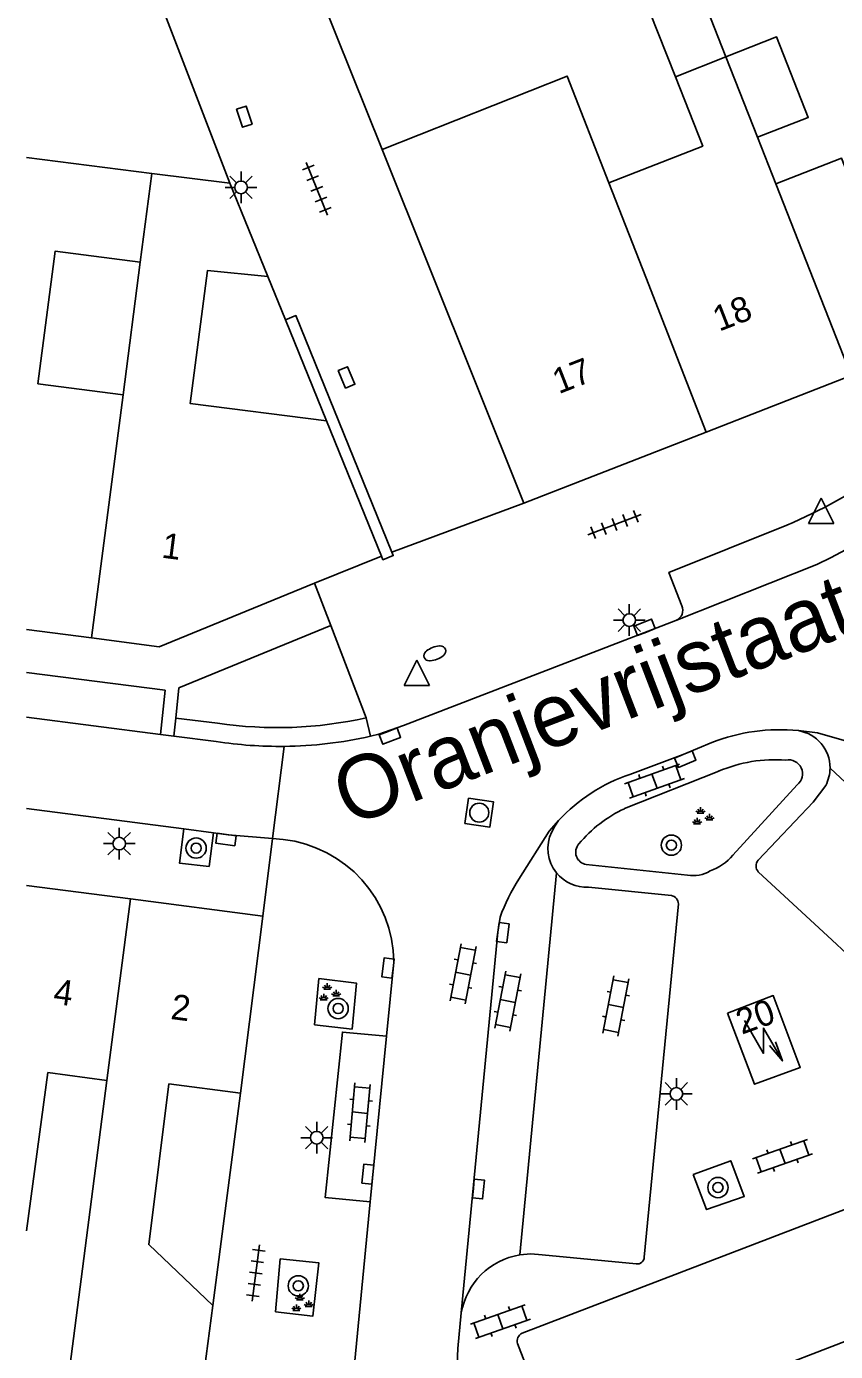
# Model space of a CAD drawing. Extents: x 132994 to 136000, y 393499 to 395512.
# Drawn here: x 133000 to 133031.9, y 395339 to 395391.3 of the extents above; entities that cross this region are included whole.
import ezdxf

# ---------------------------------------------------------------- set-up
doc = ezdxf.new("R2010")
doc.units = 0
for name, color, linetype in [('gg-afsc-erfafscheiding', 7, 'Continuous'), ('gg-afsc-muur', 7, 'Continuous'), ('gg-anno-huisnummerreeks BGT', 7, 'Continuous'), ('gg-anno-openbare ruimte label', 7, 'Continuous'), ('gg-bbg-gedigitaliseerde bebouwing', 7, 'Continuous'), ('gg-bbg-gedigitaliseerde bijgebouw', 7, 'Continuous'), ('gg-bbg-hoofdgebouw', 7, 'Continuous'), ('gg-bbg-luifel en loopbrug', 7, 'Continuous'), ('gg-bbg-tussenscheiding', 7, 'Continuous'), ('gg-knt-verharding', 7, 'Continuous'), ('gg-knt-verharding nz', 7, 'Continuous'), ('gt-grn-weggrens', 7, 'Continuous'), ('gt-symb-boom', 7, 'Continuous'), ('gt-symb-brandkraan', 7, 'Continuous'), ('gt-symb-groenvak', 7, 'Continuous'), ('gt-symb-klinker verharding', 7, 'Continuous'), ('gt-symb-kolk', 7, 'Continuous'), ('gt-symb-lichtmast', 7, 'Continuous'), ('gt-symb-rioolschacht', 7, 'Continuous'), ('gt-symb-tegel verharding', 7, 'Continuous'), ('gt-symb-trafo symbool', 7, 'Continuous'), ('gt-symb-waterafsluiter', 7, 'Continuous')]:
    doc.layers.add(name, color=color, linetype=linetype)

# ---------------------------------------------------------------- blocks, each defined once
blk = doc.blocks.new('gt0-KOLK')
at = {"layer": 'gt-symb-kolk'}
blk.add_lwpolyline([(0, 0), (0.375, 0), (0.375, 0.4), (-0.375, 0.4), (-0.375, 0), (0, 0)], dxfattribs=at)
blk = doc.blocks.new('gt0-LMAST')
at = {"layer": 'gt-symb-lichtmast'}
for p, q in [((-0.005, 0.246), (-0.005, 0.621)), ((-0.182, 0.173), (-0.447, 0.438)), ((0.172, 0.173), (0.437, 0.438)), ((-0.255, -0.004), (-0.63, -0.004)), ((-0.182, -0.181), (-0.447, -0.446)), ((-0.005, -0.254), (-0.005, -0.629)), ((0.437, -0.446), (0.172, -0.181)), ((0.245, -0.004), (0.62, -0.004))]:
    blk.add_line(p, q, dxfattribs=at)
blk.add_circle((-0.005, -0.004), 0.25, dxfattribs=at)
blk = doc.blocks.new('gt0-TEG1')
at = {"layer": 'gt-symb-tegel verharding'}
for p, q in [((-1.125, 0), (1.125, 0)), ((-0.9, -0.25), (-0.9, 0.25)), ((-0.45, -0.25), (-0.45, 0.25)), ((0, -0.25), (0, 0.25)), ((0.45, -0.25), (0.45, 0.25)), ((0.9, -0.25), (0.9, 0.25))]:
    blk.add_line(p, q, dxfattribs=at)
blk = doc.blocks.new('gt0-WAFSL')
at = {"layer": 'gt-symb-waterafsluiter'}
for p, q in [((-0.5, -0.333), (0, 0.667)), ((0, 0.667), (0.5, -0.333)), ((0.5, -0.333), (-0.5, -0.333))]:
    blk.add_line(p, q, dxfattribs=at)
blk = doc.blocks.new('gt0-BR')
at = {"layer": 'gt-symb-brandkraan'}
for centre, radius, start, end in [((-0.244, 0), 0.206, 107.5669, 252.4331), ((0.599, -2.664), 3, 106.892, 107.5669), ((0, -0.691), 0.938, 73.108, 106.892), ((-0.599, -2.664), 3, 72.4331, 73.108), ((0.244, 0), 0.206, 287.567, 72.4331), ((0.599, 2.664), 3, 252.4331, 253.108), ((0, 0.691), 0.938, 253.108, 286.8921), ((-0.599, 2.664), 3, 286.8921, 287.567)]:
    blk.add_arc(centre, radius, start, end, dxfattribs=at)
blk = doc.blocks.new('gt0-GRVAK')
at = {"layer": 'gt-symb-groenvak'}
for p, q in [((-0.11, 0.189), (-0.228, 0.24)), ((-0.182, 0.153), (0.088, 0.153)), ((-0.091, 0.211), (-0.156, 0.322)), ((-0.047, 0.214), (-0.047, 0.393)), ((-0.004, 0.211), (0.061, 0.322)), ((0.015, 0.189), (0.133, 0.24)), ((0.262, -0.052), (0.197, 0.059)), ((0.305, -0.049), (0.305, 0.13)), ((0.349, -0.052), (0.414, 0.059)), ((-0.245, -0.228), (-0.363, -0.177)), ((-0.318, -0.264), (-0.047, -0.264)), ((-0.226, -0.206), (-0.291, -0.095)), ((-0.183, -0.203), (-0.183, -0.024)), ((-0.139, -0.206), (-0.074, -0.095)), ((-0.12, -0.228), (-0.002, -0.177)), ((0.243, -0.074), (0.125, -0.023)), ((0.17, -0.11), (0.441, -0.11)), ((0.368, -0.074), (0.486, -0.023))]:
    blk.add_line(p, q, dxfattribs=at)
blk = doc.blocks.new('gt0-BOOM')
at = {"layer": 'gt-symb-boom'}
for radius in [0.4, 0.2]:
    blk.add_circle((0, 0), radius, dxfattribs=at)
blk = doc.blocks.new('gt0-HSP')
at = {"layer": 'gt-symb-trafo symbool'}
for points in [[(0.771, 0.746), (-0.529, -0.004), (0.471, -0.004), (-0.829, -0.754)], [(-0.217, -0.24), (-0.829, -0.754), (-0.077, -0.48)]]:
    blk.add_lwpolyline(points, dxfattribs=at)
blk = doc.blocks.new('gt0-KL1')
at = {"layer": 'gt-symb-klinker verharding'}
for p, q in [((-1.15, 0.3), (1.15, 0.3)), ((-1, -0.3), (-1, 0.3)), ((-0.5, 0.3), (-0.5, 0.45)), ((0, -0.3), (0, 0.3)), ((0.5, 0.3), (0.5, 0.45)), ((1, -0.3), (1, 0.3)), ((-1.15, -0.3), (1.15, -0.3)), ((-0.5, -0.45), (-0.5, -0.3)), ((0.5, -0.45), (0.5, -0.3))]:
    blk.add_line(p, q, dxfattribs=at)
blk = doc.blocks.new('gt0-RS')
at = {"layer": 'gt-symb-rioolschacht'}
blk.add_lwpolyline([(-0.5, -0.5), (0.5, -0.5), (0.5, 0.5), (-0.5, 0.5)], close=True, dxfattribs=at)
blk.add_circle((0, 0), 0.375, dxfattribs=at)

msp = doc.modelspace()

# ---------------------------------------------------------------- linework, layer by layer
at = {"layer": 'gg-afsc-erfafscheiding'}
msp.add_line((133011.425, 395392.988), (133014.031, 395386.48), dxfattribs=at)
at = {"layer": 'gg-afsc-muur'}
for p, q in [((133008.03, 395385.145), (133003.697, 395396.435)), ((133009.529, 395381.461), (133010.22, 395379.755)), ((133010.22, 395379.755), (133011.838, 395375.763)), ((133008.45, 395349.22), (133007.35, 395340.833))]:
    msp.add_line(p, q, dxfattribs=at)
at = {"layer": 'gg-bbg-gedigitaliseerde bebouwing'}
for p, q in [((133025.611, 395389.356), (133027.607, 395390.141)), ((133028.856, 395386.964), (133029.578, 395385.124)), ((133004.49, 395382.025), (133003.812, 395376.796)), ((133001.705, 395338.403), (133003.17, 395349.719))]:
    msp.add_line(p, q, dxfattribs=at)
for points in [[(133014.031, 395386.48), (133021.341, 395389.381), (133022.986, 395385.162)], [(133022.986, 395385.162), (133026.687, 395386.616), (133025.611, 395389.356)], [(133029.578, 395385.124), (133032.169, 395386.133), (133032.704, 395384.759), (133035.66, 395385.91)], [(133003.812, 395376.796), (133000.447, 395377.233), (133001.125, 395382.461), (133004.49, 395382.025)], [(133000, 395343.773), (133000.842, 395350.031), (133003.17, 395349.719)]]:
    msp.add_lwpolyline(points, dxfattribs=at)
at = {"layer": 'gg-bbg-gedigitaliseerde bijgebouw'}
msp.add_lwpolyline([(133028.856, 395386.964), (133030.853, 395387.748), (133029.605, 395390.925), (133027.607, 395390.141)], dxfattribs=at)
at = {"layer": 'gg-bbg-hoofdgebouw'}
for p, q in [((133000, 395386.17), (133004.946, 395385.539)), ((133019.63, 395372.52), (133014.031, 395386.48)), ((133004.946, 395385.539), (133008.03, 395385.145)), ((133009.529, 395381.461), (133008.03, 395385.145)), ((133011.838, 395375.763), (133014.007, 395370.426)), ((133026.822, 395375.323), (133019.63, 395372.52)), ((133011.367, 395369.349), (133014.007, 395370.426)), ((133000, 395367.52), (133002.566, 395367.19)), ((133000, 395357.419), (133004.098, 395356.888)), ((133004.098, 395356.888), (133009.33, 395356.21)), ((133009.33, 395356.21), (133008.45, 395349.22)), ((133006.942, 395337.72), (133007.35, 395340.833))]:
    msp.add_line(p, q, dxfattribs=at)
for points in [[(133011.838, 395375.763), (133006.455, 395376.453), (133007.139, 395381.7), (133009.529, 395381.461)], [(133032.551, 395377.556), (133028.342, 395375.916), (133026.822, 395375.323)], [(133002.566, 395367.19), (133005.235, 395366.846), (133011.367, 395369.349)], [(133027.67, 395352.37), (133029.47, 395353.07), (133030.54, 395350.23), (133028.73, 395349.57), (133027.67, 395352.37)], [(133008.45, 395349.22), (133005.62, 395349.58), (133004.822, 395343.236), (133007.35, 395340.833)]]:
    msp.add_lwpolyline(points, dxfattribs=at)
at = {"layer": 'gg-bbg-luifel en loopbrug'}
msp.add_lwpolyline([(133025.611, 395389.356), (133024.251, 395392.816), (133026.248, 395393.601), (133027.607, 395390.141)], dxfattribs=at)
at = {"layer": 'gg-bbg-tussenscheiding'}
for p, q in [((133027.607, 395390.141), (133028.856, 395386.964)), ((133004.49, 395382.025), (133004.946, 395385.539)), ((133022.986, 395385.162), (133024.438, 395381.439)), ((133032.551, 395377.556), (133029.578, 395385.124)), ((133026.822, 395375.323), (133024.438, 395381.439)), ((133002.566, 395367.19), (133003.812, 395376.796)), ((133004.098, 395356.888), (133003.17, 395349.719))]:
    msp.add_line(p, q, dxfattribs=at)
at = {"layer": 'gg-knt-verharding'}
for p, q in [((133012.009, 395367.678), (133013.407, 395364.04)), ((133005.898, 395364.022), (133005.808, 395363.316)), ((133005.898, 395364.022), (133007.537, 395363.829)), ((133013.407, 395364.04), (133013.571, 395363.309)), ((133005.808, 395363.316), (133005.282, 395363.384)), ((133007.487, 395363.101), (133005.808, 395363.316)), ((133023.605, 395360.45), (133027.318, 395361.927)), ((133030.419, 395361.395), (133027.882, 395358.609)), ((133000, 395360.455), (133006.212, 395359.649)), ((133006.212, 395359.649), (133007.377, 395359.498)), ((133009.715, 395359.269), (133010.129, 395359.233)), ((133022.093, 395358.25), (133026.084, 395357.821)), ((133025.459, 395357.016), (133022.185, 395357.35)), ((133024.382, 395342.739), (133025.728, 395356.689)), ((133014.497, 395354.385), (133014.203, 395351.469)), ((133019.563, 395339.738), (133043.881, 395349.068)), ((133013.569, 395344.929), (133012.777, 395336.763)), ((133017.161, 395340.535), (133017.027, 395339.132)), ((133020.512, 395336.403), (133019.38, 395339.324))]:
    msp.add_line(p, q, dxfattribs=at)
for points in [[(133010.22, 395379.755), (133010.634, 395379.923), (133014.42, 395370.58)], [(133030.007, 395371.645), (133025.353, 395369.779), (133025.867, 395368.463)], [(133014.42, 395370.58), (133014.475, 395370.444), (133014.067, 395370.279), (133014.007, 395370.426)], [(133025.633, 395367.883), (133014.873, 395363.73), (133013.905, 395363.388), (133013.571, 395363.309)], [(133005.898, 395364.022), (133006.018, 395365.218), (133012.009, 395367.678)], [(133005.282, 395363.384), (133005.469, 395365.124), (133000, 395365.833)], [(133027.048, 395363.065), (133025.921, 395362.594), (133023.814, 395361.8)], [(133028.878, 395358.413), (133031.046, 395360.702), (133031.543, 395361.368)], [(133020.727, 395359.534), (133020.85, 395359.765), (133021, 395359.979)], [(133006.212, 395359.649), (133006.036, 395358.3), (133007.204, 395358.169), (133007.377, 395359.498)], [(133009.715, 395359.269), (133007.965, 395359.421), (133007.377, 395359.498)], [(133039.15, 395348.406), (133031.801, 395355.255), (133028.883, 395357.952)], [(133011.37, 395351.918), (133012.85, 395351.746), (133013.022, 395353.565), (133011.542, 395353.737), (133011.37, 395351.918)], [(133014.203, 395351.469), (133012.471, 395351.625), (133011.786, 395345.097), (133013.569, 395344.929)], [(133026.308, 395346.005), (133026.841, 395344.615), (133028.33, 395345.133), (133027.795, 395346.543), (133026.308, 395346.005)], [(133024.062, 395342.47), (133020.357, 395342.832), (133019.911, 395342.864), (133019.467, 395342.828)], [(133009.826, 395340.577), (133011.301, 395340.41), (133011.531, 395342.521), (133010.014, 395342.669), (133009.826, 395340.577)]]:
    msp.add_lwpolyline(points, dxfattribs=at)
for centre, radius, start, end in [((133021.106, 395392.421), 22.602, 293.1921, 315.334), ((133025.468, 395368.287), 0.436, 292.2492, 23.8077), ((133009.911, 395379.543), 15.893, 261.4095, 282.7078), ((133009.985, 395379.333), 16.423, 261.2511, 270.6595), ((133009.981, 395379.25), 16.34, 270.6751, 282.6898), ((133029.741, 395356.074), 7.492, 84.4723, 111.0685), ((133030.225, 395362.06), 1.49, 359.7727, 80.8008), ((133029.55, 395356.702), 5.682, 85.7228, 113.1319), ((133030.079, 395361.828), 0.55, 308.1297, 101.0242), ((133030.187, 395362.073), 1.528, 332.5455, 359.3034), ((133025.948, 395355.418), 6.729, 108.4859, 137.3296), ((133025.722, 395355.846), 5.067, 114.6888, 140.6327), ((133022.095, 395358.873), 1.519, 154.2168, 219.1002), ((133009.58, 395354.347), 4.917, 0.4449, 83.5922), ((133022.16, 395358.73), 0.485, 137.1629, 262.1089), ((133026.241, 395360.033), 2.172, 289.9615, 319.0501), ((133029.144, 395358.185), 0.35, 139.4792, 221.7636), ((133022.092, 395358.848), 1.501, 218.4423, 273.5574), ((133026.296, 395359.163), 1.359, 261.0308, 300.3854), ((133025.402, 395356.695), 0.326, 358.9111, 79.9724), ((133019.926, 395340.061), 2.805, 99.4095, 170.2666), ((133024.095, 395342.756), 0.288, 263.5156, 356.5869), ((133019.718, 395339.422), 0.352, 116.1433, 196.1631), ((133021.786, 395338.673), 4.781, 174.4878, 231.0728)]:
    msp.add_arc(centre, radius, start, end, dxfattribs=at)
at = {"layer": 'gg-knt-verharding nz'}
for p, q in [((133000, 395364.065), (133005.282, 395363.384)), ((133031.715, 395362.054), (133042.784, 395351.686)), ((133020.916, 395357.915), (133019.467, 395342.828)), ((133014.203, 395351.469), (133013.569, 395344.929)), ((133020.541, 395334.887), (133046.32, 395344.8))]:
    msp.add_line(p, q, dxfattribs=at)
for points in [[(133025.633, 395367.883), (133031.197, 395370.09), (133031.764, 395370.363), (133032.323, 395370.665), (133033.233, 395371.205)], [(133032.728, 395363.011), (133031.22, 395363.439), (133030.463, 395363.531)], [(133021, 395359.979), (133020.633, 395359.565), (133019.429, 395357.668)], [(133018.69, 395356.166), (133018.604, 395355.578), (133017.161, 395340.535)]]:
    msp.add_lwpolyline(points, dxfattribs=at)
msp.add_arc((133026.597, 395353.209), 8.442, 148.1123, 159.4924, dxfattribs=at)
at = {"layer": 'gt-grn-weggrens'}
for p, q in [((133019.63, 395372.52), (133014.42, 395370.58)), ((133012.009, 395367.678), (133011.367, 395369.349)), ((133010.174, 395362.911), (133009.715, 395359.269)), ((133009.715, 395359.269), (133009.33, 395356.21))]:
    msp.add_line(p, q, dxfattribs=at)

# ---------------------------------------------------------------- block references
at = {"layer": 'gt-symb-boom'}
for p in [(133006.693, 395358.894), (133025.45, 395359.01), (133012.297, 395352.557), (133027.291, 395345.488), (133010.727, 395341.607)]:
    msp.add_blockref('gt0-BOOM', p, dxfattribs=at)
at = {"layer": 'gt-symb-brandkraan', "rotation": 21.28016631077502}
msp.add_blockref('gt0-BR', (133016.115, 395366.583), dxfattribs=at)
at = {"layer": 'gt-symb-groenvak'}
for p in [(133026.649, 395360.113), (133011.914, 395353.163), (133010.834, 395340.897)]:
    msp.add_blockref('gt0-GRVAK', p, dxfattribs=at)
at = {"layer": 'gt-symb-klinker verharding'}
for p, rotation in [((133024.784, 395361.536), 19.503573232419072), ((133017.229, 395353.931), -100.89418298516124), ((133018.995, 395352.852), -100.89418298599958), ((133023.263, 395352.656), -100.89418298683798), ((133013.159, 395348.445), -95.16330681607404), ((133029.838, 395346.719), 19.50357323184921), ((133018.701, 395340.194), 19.503573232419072)]:
    msp.add_blockref('gt0-KL1', p, dxfattribs=dict(at, rotation=rotation))
at = {"layer": 'gt-symb-kolk'}
for p, rotation in [((133008.405, 395387.715), -71.81873102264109), ((133012.45, 395377.402), -67.04963699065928), ((133024.468, 395367.426), 21.407739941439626), ((133014.272, 395363.503), -159.26285189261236), ((133025.921, 395362.594), -157.31744007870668), ((133007.898, 395359.43), 172.53867183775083), ((133018.604, 395355.578), -97.43732275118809), ((133014.466, 395354.135), 82.87498365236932), ((133013.67, 395345.997), 84.6085366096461), ((133017.638, 395345.449), -95.44721780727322)]:
    msp.add_blockref('gt0-KOLK', p, dxfattribs=dict(at, rotation=rotation))
at = {"layer": 'gt-symb-lichtmast'}
for p in [(133008.472, 395384.987), (133023.795, 395367.898), (133003.662, 395359.073), (133025.653, 395349.192), (133011.458, 395347.461)]:
    msp.add_blockref('gt0-LMAST', p, dxfattribs=at)
at = {"layer": 'gt-symb-rioolschacht', "rotation": -98.27589282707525}
msp.add_blockref('gt0-RS', (133017.869, 395360.292), dxfattribs=at)
at = {"layer": 'gt-symb-tegel verharding'}
for p, rotation in [((133011.458, 395384.929), 111.84397692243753), ((133023.206, 395371.669), 21.04574081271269), ((133009.049, 395342.114), -97.53025334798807)]:
    msp.add_blockref('gt0-TEG1', p, dxfattribs=dict(at, rotation=rotation))
at = {"layer": 'gt-symb-trafo symbool', "rotation": 90}
msp.add_blockref('gt0-HSP', (133029.082, 395351.317), dxfattribs=at)
at = {"layer": 'gt-symb-waterafsluiter'}
for p in [(133031.364, 395372.039), (133015.405, 395365.643)]:
    msp.add_blockref('gt0-WAFSL', p, dxfattribs=at)

# ---------------------------------------------------------------- texts
at = {"layer": 'gg-anno-huisnummerreeks BGT'}
for s, rotation, p in [('18', 21.3, (133027.336, 395379.281)), ('17', 21.3, (133021.006, 395376.813)), ('1', 352.7, (133005.3, 395370.366)), ('4', 352.6, (133001.028, 395352.748)), ('2', 352.6, (133005.661, 395352.148)), ('20', 19.9, (133028.231, 395351.52))]:
    msp.add_text(s, height=1, rotation=rotation, dxfattribs=at).set_placement(p)
at = {"layer": 'gg-anno-openbare ruimte label'}
for rotation, p in [(21, (133012.725, 395359.728)), (20.4, (133026.015, 395331.343))]:
    msp.add_text('Oranjevrijstaatplein', height=2.5, rotation=rotation, dxfattribs=at).set_placement(p)

doc.saveas('drawing.dxf')
